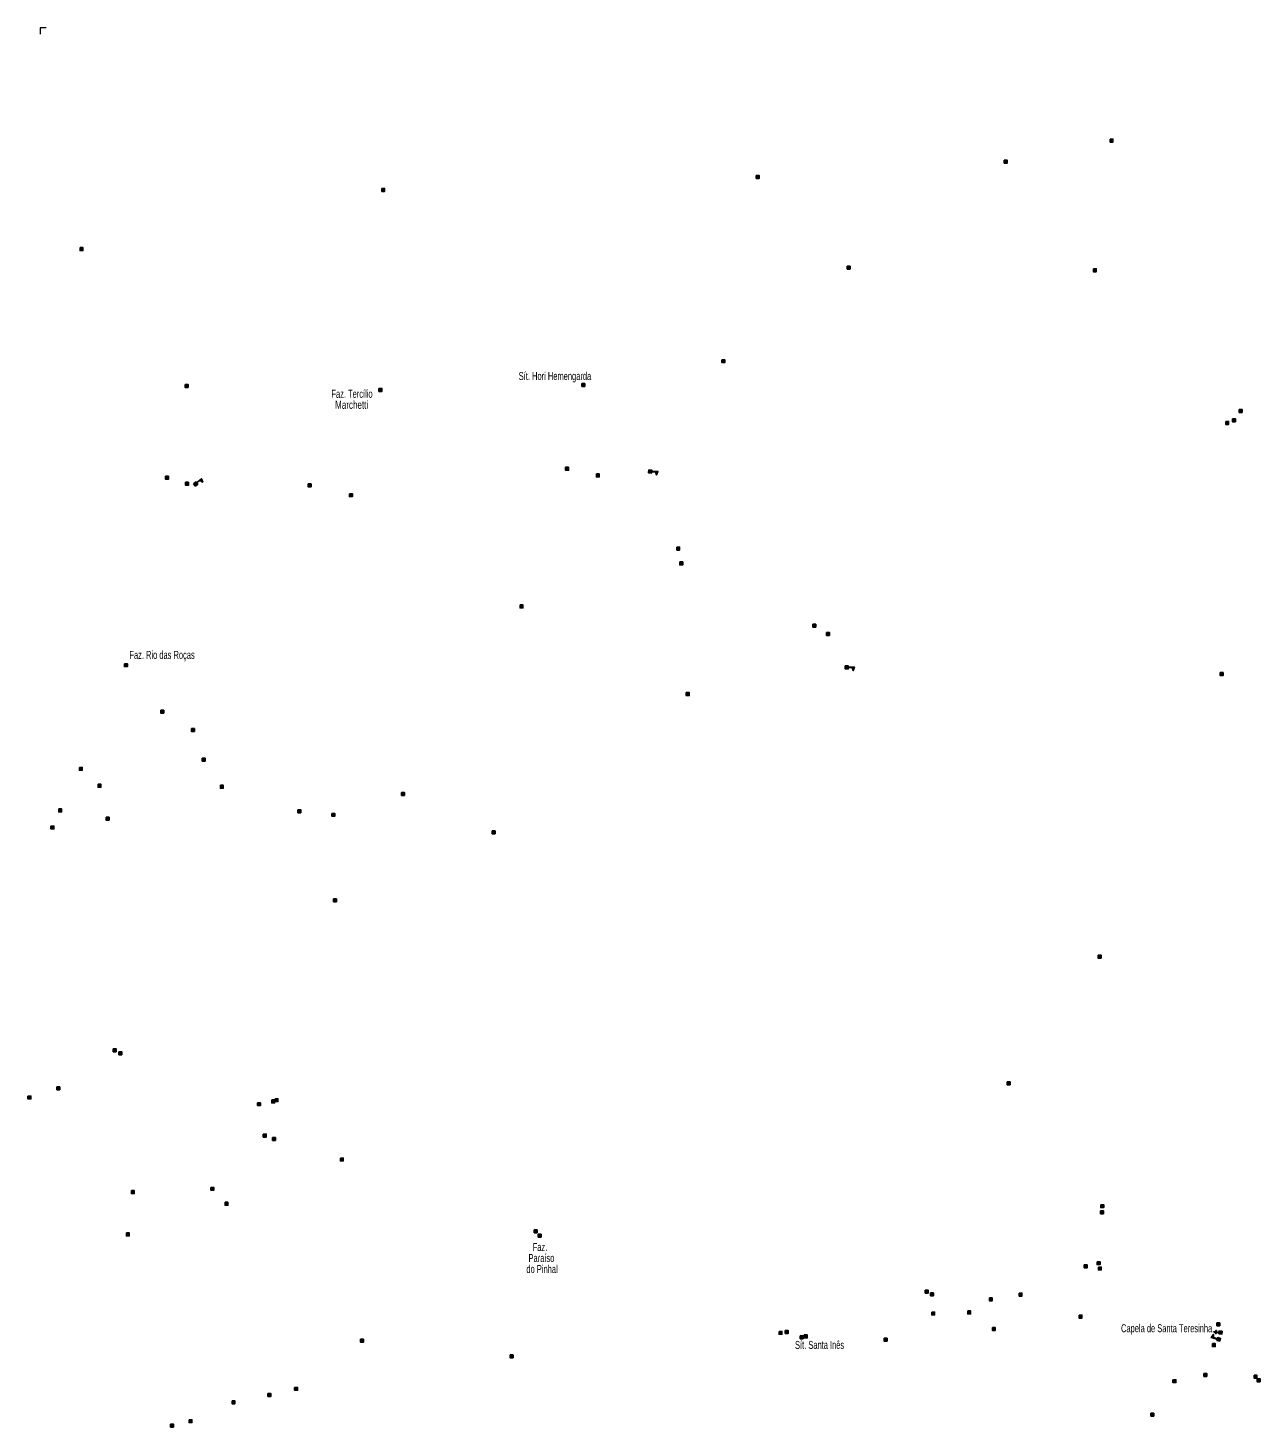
# Model space of a CAD drawing. Extents: x 649.2 to 674.4, y 7040 to 7068.1.
# Drawn here: x 649.37 to 661.68, y 7054.07 to 7068.06 of the extents above; entities that cross this region are included whole.
import ezdxf
from ezdxf.enums import TextEntityAlignment as Align

# ---------------------------------------------------------------- set-up
doc = ezdxf.new("R2010")
doc.units = 0
doc.header["$LTSCALE"] = 0.032
for name, color, linetype, lineweight in [('2', 7, 'Continuous', 25), ('4', 7, 'Continuous', 25), ('6', 7, 'Continuous', 25), ('63', 7, 'Continuous', 13)]:
    doc.layers.add(name, color=color, linetype=linetype, lineweight=lineweight)
doc.layers.add('61', color=7, linetype='Continuous')

msp = doc.modelspace()

# ---------------------------------------------------------------- hatches: boundary and pattern name
at = {"layer": '2'}
for points in [[(660.1834, 7066.9508), (660.2124, 7066.9508), (660.2124, 7066.9218), (660.1834, 7066.9218)], [(659.1263, 7066.7397), (659.1553, 7066.7397), (659.1553, 7066.7107), (659.1263, 7066.7107)], [(656.6475, 7066.5866), (656.6765, 7066.5866), (656.6765, 7066.5576), (656.6475, 7066.5576)], [(652.9028, 7066.4573), (652.9318, 7066.4573), (652.9318, 7066.4283), (652.9028, 7066.4283)], [(649.8868, 7065.866), (649.9158, 7065.866), (649.9158, 7065.837), (649.8868, 7065.837)], [(657.5563, 7065.6798), (657.5853, 7065.6798), (657.5853, 7065.6508), (657.5563, 7065.6508)], [(660.017, 7065.6539), (660.046, 7065.6539), (660.046, 7065.6249), (660.017, 7065.6249)], [(656.3032, 7064.7455), (656.3322, 7064.7455), (656.3322, 7064.7165), (656.3032, 7064.7165)], [(650.9374, 7064.498), (650.9664, 7064.498), (650.9664, 7064.469), (650.9374, 7064.469)], [(652.8752, 7064.4576), (652.9042, 7064.4576), (652.9042, 7064.4286), (652.8752, 7064.4286)], [(654.9037, 7064.5068), (654.9327, 7064.5068), (654.9327, 7064.4778), (654.9037, 7064.4778)], [(661.34, 7064.1278), (661.369, 7064.1278), (661.369, 7064.0988), (661.34, 7064.0988)], [(661.4079, 7064.1548), (661.4369, 7064.1548), (661.4369, 7064.1258), (661.4079, 7064.1258)], [(661.474, 7064.2479), (661.503, 7064.2479), (661.503, 7064.2189), (661.474, 7064.2189)], [(650.7419, 7063.5796), (650.7709, 7063.5796), (650.7709, 7063.5506), (650.7419, 7063.5506)], [(654.7412, 7063.6694), (654.7702, 7063.6694), (654.7702, 7063.6404), (654.7412, 7063.6404)], [(655.0488, 7063.6027), (655.0778, 7063.6027), (655.0778, 7063.5737), (655.0488, 7063.5737)], [(650.9419, 7063.5198), (650.9709, 7063.5198), (650.9709, 7063.4908), (650.9419, 7063.4908)], [(652.1674, 7063.5035), (652.1964, 7063.5035), (652.1964, 7063.4745), (652.1674, 7063.4745)], [(652.5802, 7063.406), (652.6092, 7063.406), (652.6092, 7063.377), (652.5802, 7063.377)], [(655.8518, 7062.8716), (655.8808, 7062.8716), (655.8808, 7062.8426), (655.8518, 7062.8426)], [(655.8824, 7062.7231), (655.9114, 7062.7231), (655.9114, 7062.6941), (655.8824, 7062.6941)], [(654.2856, 7062.2937), (654.3146, 7062.2937), (654.3146, 7062.2647), (654.2856, 7062.2647)], [(657.2126, 7062.1007), (657.2416, 7062.1007), (657.2416, 7062.0717), (657.2126, 7062.0717)], [(657.3488, 7062.0185), (657.3778, 7062.0185), (657.3778, 7061.9895), (657.3488, 7061.9895)], [(650.3309, 7061.7062), (650.3599, 7061.7062), (650.3599, 7061.6772), (650.3309, 7061.6772)], [(661.2847, 7061.6171), (661.3137, 7061.6171), (661.3137, 7061.5881), (661.2847, 7061.5881)], [(655.9473, 7061.4167), (655.9763, 7061.4167), (655.9763, 7061.3877), (655.9473, 7061.3877)], [(650.6944, 7061.2416), (650.7234, 7061.2416), (650.7234, 7061.2126), (650.6944, 7061.2126)], [(651.001, 7061.058), (651.03, 7061.058), (651.03, 7061.029), (651.001, 7061.029)], [(649.8801, 7060.6699), (649.9091, 7060.6699), (649.9091, 7060.6409), (649.8801, 7060.6409)], [(651.1092, 7060.7612), (651.1382, 7060.7612), (651.1382, 7060.7322), (651.1092, 7060.7322)], [(650.0672, 7060.5006), (650.0962, 7060.5006), (650.0962, 7060.4716), (650.0672, 7060.4716)], [(651.2895, 7060.4907), (651.3185, 7060.4907), (651.3185, 7060.4617), (651.2895, 7060.4617)], [(653.1014, 7060.4191), (653.1304, 7060.4191), (653.1304, 7060.3901), (653.1014, 7060.3901)], [(649.6739, 7060.2536), (649.7029, 7060.2536), (649.7029, 7060.2246), (649.6739, 7060.2246)], [(652.0647, 7060.2458), (652.0937, 7060.2458), (652.0937, 7060.2168), (652.0647, 7060.2168)], [(652.4044, 7060.2102), (652.4334, 7060.2102), (652.4334, 7060.1812), (652.4044, 7060.1812)], [(649.5962, 7060.083), (649.6252, 7060.083), (649.6252, 7060.054), (649.5962, 7060.054)], [(650.1487, 7060.1709), (650.1777, 7060.1709), (650.1777, 7060.1419), (650.1487, 7060.1419)], [(654.0066, 7060.0351), (654.0356, 7060.0351), (654.0356, 7060.0061), (654.0066, 7060.0061)], [(652.4213, 7059.3547), (652.4503, 7059.3547), (652.4503, 7059.3257), (652.4213, 7059.3257)], [(660.0644, 7058.7923), (660.0934, 7058.7923), (660.0934, 7058.7633), (660.0644, 7058.7633)], [(650.2189, 7057.8561), (650.2479, 7057.8561), (650.2479, 7057.8271), (650.2189, 7057.8271)], [(650.2753, 7057.8259), (650.3043, 7057.8259), (650.3043, 7057.7969), (650.2753, 7057.7969)], [(649.6558, 7057.4756), (649.6848, 7057.4756), (649.6848, 7057.4466), (649.6558, 7057.4466)], [(659.155, 7057.5266), (659.184, 7057.5266), (659.184, 7057.4976), (659.155, 7057.4976)], [(649.3665, 7057.384), (649.3955, 7057.384), (649.3955, 7057.355), (649.3665, 7057.355)], [(651.6616, 7057.317), (651.6906, 7057.317), (651.6906, 7057.288), (651.6616, 7057.288)], [(651.8034, 7057.3449), (651.8324, 7057.3449), (651.8324, 7057.3159), (651.8034, 7057.3159)], [(651.8365, 7057.3568), (651.8655, 7057.3568), (651.8655, 7057.3278), (651.8365, 7057.3278)], [(651.7186, 7057.0029), (651.7476, 7057.0029), (651.7476, 7056.9739), (651.7186, 7056.9739)], [(651.8114, 7056.9698), (651.8404, 7056.9698), (651.8404, 7056.9408), (651.8114, 7056.9408)], [(652.4896, 7056.7639), (652.5186, 7056.7639), (652.5186, 7056.7349), (652.4896, 7056.7349)], [(650.4005, 7056.4384), (650.4295, 7056.4384), (650.4295, 7056.4094), (650.4005, 7056.4094)], [(651.195, 7056.4706), (651.224, 7056.4706), (651.224, 7056.4416), (651.195, 7056.4416)], [(651.3364, 7056.3216), (651.3654, 7056.3216), (651.3654, 7056.2926), (651.3364, 7056.2926)], [(660.0915, 7056.2973), (660.1205, 7056.2973), (660.1205, 7056.2683), (660.0915, 7056.2683)], [(660.0884, 7056.2363), (660.1174, 7056.2363), (660.1174, 7056.2073), (660.0884, 7056.2073)], [(650.35, 7056.0147), (650.379, 7056.0147), (650.379, 7055.9857), (650.35, 7055.9857)], [(654.4274, 7056.0462), (654.4564, 7056.0462), (654.4564, 7056.0172), (654.4274, 7056.0172)], [(654.4677, 7056.0023), (654.4967, 7056.0023), (654.4967, 7055.9733), (654.4677, 7055.9733)], [(659.9262, 7055.6959), (659.9552, 7055.6959), (659.9552, 7055.6669), (659.9262, 7055.6669)], [(660.0549, 7055.7271), (660.0839, 7055.7271), (660.0839, 7055.6981), (660.0549, 7055.6981)], [(660.0667, 7055.674), (660.0957, 7055.674), (660.0957, 7055.645), (660.0667, 7055.645)], [(658.3357, 7055.4436), (658.3647, 7055.4436), (658.3647, 7055.4146), (658.3357, 7055.4146)], [(658.389, 7055.4164), (658.418, 7055.4164), (658.418, 7055.3874), (658.389, 7055.3874)], [(658.9776, 7055.3656), (659.0066, 7055.3656), (659.0066, 7055.3366), (658.9776, 7055.3366)], [(659.2736, 7055.4138), (659.3026, 7055.4138), (659.3026, 7055.3848), (659.2736, 7055.3848)], [(658.4009, 7055.2248), (658.4299, 7055.2248), (658.4299, 7055.1958), (658.4009, 7055.1958)], [(658.7611, 7055.2351), (658.7901, 7055.2351), (658.7901, 7055.2061), (658.7611, 7055.2061)], [(659.8735, 7055.1934), (659.9025, 7055.1934), (659.9025, 7055.1644), (659.8735, 7055.1644)], [(656.9372, 7055.0396), (656.9662, 7055.0396), (656.9662, 7055.0106), (656.9372, 7055.0106)], [(659.0076, 7055.0695), (659.0366, 7055.0695), (659.0366, 7055.0405), (659.0076, 7055.0405)], [(661.2519, 7055.1157), (661.2809, 7055.1157), (661.2809, 7055.0867), (661.2519, 7055.0867)], [(652.6913, 7054.9523), (652.7203, 7054.9523), (652.7203, 7054.9233), (652.6913, 7054.9233)], [(656.8746, 7055.0309), (656.9036, 7055.0309), (656.9036, 7055.0019), (656.8746, 7055.0019)], [(657.0866, 7054.9858), (657.1156, 7054.9858), (657.1156, 7054.9568), (657.0866, 7054.9568)], [(657.127, 7054.9952), (657.156, 7054.9952), (657.156, 7054.9662), (657.127, 7054.9662)], [(657.925, 7054.9623), (657.954, 7054.9623), (657.954, 7054.9333), (657.925, 7054.9333)], [(661.2066, 7054.9085), (661.2356, 7054.9085), (661.2356, 7054.8795), (661.2066, 7054.8795)], [(654.1863, 7054.7962), (654.2153, 7054.7962), (654.2153, 7054.7672), (654.1863, 7054.7672)], [(660.8128, 7054.5476), (660.8418, 7054.5476), (660.8418, 7054.5186), (660.8128, 7054.5186)], [(661.1216, 7054.6107), (661.1506, 7054.6107), (661.1506, 7054.5817), (661.1216, 7054.5817)], [(661.6238, 7054.5929), (661.6528, 7054.5929), (661.6528, 7054.5639), (661.6238, 7054.5639)], [(661.654, 7054.5572), (661.683, 7054.5572), (661.683, 7054.5282), (661.654, 7054.5282)], [(651.4061, 7054.3365), (651.4351, 7054.3365), (651.4351, 7054.3075), (651.4061, 7054.3075)], [(651.7656, 7054.4096), (651.7946, 7054.4096), (651.7946, 7054.3806), (651.7656, 7054.3806)], [(652.032, 7054.471), (652.061, 7054.471), (652.061, 7054.442), (652.032, 7054.442)], [(660.592, 7054.2125), (660.621, 7054.2125), (660.621, 7054.1835), (660.592, 7054.1835)], [(650.792, 7054.104), (650.821, 7054.104), (650.821, 7054.075), (650.792, 7054.075)], [(650.9767, 7054.1476), (651.0057, 7054.1476), (651.0057, 7054.1186), (650.9767, 7054.1186)]]:
    msp.add_hatch(color=256, dxfattribs=at).paths.add_polyline_path(points)
at = {"layer": '4'}
for points in [[(655.5717, 7063.6429), (655.6017, 7063.6422), (655.601, 7063.6122), (655.571, 7063.6129)], [(651.0219, 7063.5044), (651.0445, 7063.5241), (651.0643, 7063.5015), (651.0417, 7063.4818)], [(657.5364, 7061.6845), (657.5664, 7061.6847), (657.5666, 7061.6547), (657.5366, 7061.6545)], [(661.2804, 7054.9321), (661.2516, 7054.9405), (661.26, 7054.9693), (661.2888, 7054.9609)]]:
    msp.add_hatch(color=256, dxfattribs=at).paths.add_polyline_path(points)
at = {"layer": '6'}
for points in [[(661.273, 7055.0236), (661.2726, 7055.0186), (661.2452, 7055.0214), (661.2439, 7055.0089), (661.2389, 7055.0095), (661.2402, 7055.0218), (661.2228, 7055.0237), (661.2233, 7055.0286), (661.2407, 7055.0268), (661.242, 7055.0393), (661.2469, 7055.0388), (661.2457, 7055.0264)], [(661.2713, 7055.0062), (661.3012, 7055.0031), (661.3042, 7055.033), (661.2743, 7055.036)]]:
    msp.add_hatch(color=256, dxfattribs=at).paths.add_polyline_path(points)

# ---------------------------------------------------------------- linework, layer by layer
at = {"layer": '2'}
for points in [[(660.1834, 7066.9508), (660.2124, 7066.9508), (660.2124, 7066.9218), (660.1834, 7066.9218)], [(659.1263, 7066.7397), (659.1553, 7066.7397), (659.1553, 7066.7107), (659.1263, 7066.7107)], [(656.6475, 7066.5866), (656.6765, 7066.5866), (656.6765, 7066.5576), (656.6475, 7066.5576)], [(652.9028, 7066.4573), (652.9318, 7066.4573), (652.9318, 7066.4283), (652.9028, 7066.4283)], [(649.8868, 7065.866), (649.9158, 7065.866), (649.9158, 7065.837), (649.8868, 7065.837)], [(657.5563, 7065.6798), (657.5853, 7065.6798), (657.5853, 7065.6508), (657.5563, 7065.6508)], [(660.017, 7065.6539), (660.046, 7065.6539), (660.046, 7065.6249), (660.017, 7065.6249)], [(656.3032, 7064.7455), (656.3322, 7064.7455), (656.3322, 7064.7165), (656.3032, 7064.7165)], [(650.9374, 7064.498), (650.9664, 7064.498), (650.9664, 7064.469), (650.9374, 7064.469)], [(652.8752, 7064.4576), (652.9042, 7064.4576), (652.9042, 7064.4286), (652.8752, 7064.4286)], [(654.9037, 7064.5068), (654.9327, 7064.5068), (654.9327, 7064.4778), (654.9037, 7064.4778)], [(661.34, 7064.1278), (661.369, 7064.1278), (661.369, 7064.0988), (661.34, 7064.0988)], [(661.4079, 7064.1548), (661.4369, 7064.1548), (661.4369, 7064.1258), (661.4079, 7064.1258)], [(661.474, 7064.2479), (661.503, 7064.2479), (661.503, 7064.2189), (661.474, 7064.2189)], [(650.7419, 7063.5796), (650.7709, 7063.5796), (650.7709, 7063.5506), (650.7419, 7063.5506)], [(654.7412, 7063.6694), (654.7702, 7063.6694), (654.7702, 7063.6404), (654.7412, 7063.6404)], [(655.0488, 7063.6027), (655.0778, 7063.6027), (655.0778, 7063.5737), (655.0488, 7063.5737)], [(650.9419, 7063.5198), (650.9709, 7063.5198), (650.9709, 7063.4908), (650.9419, 7063.4908)], [(652.1674, 7063.5035), (652.1964, 7063.5035), (652.1964, 7063.4745), (652.1674, 7063.4745)], [(652.5802, 7063.406), (652.6092, 7063.406), (652.6092, 7063.377), (652.5802, 7063.377)], [(655.8518, 7062.8716), (655.8808, 7062.8716), (655.8808, 7062.8426), (655.8518, 7062.8426)], [(655.8824, 7062.7231), (655.9114, 7062.7231), (655.9114, 7062.6941), (655.8824, 7062.6941)], [(654.2856, 7062.2937), (654.3146, 7062.2937), (654.3146, 7062.2647), (654.2856, 7062.2647)], [(657.2126, 7062.1007), (657.2416, 7062.1007), (657.2416, 7062.0717), (657.2126, 7062.0717)], [(657.3488, 7062.0185), (657.3778, 7062.0185), (657.3778, 7061.9895), (657.3488, 7061.9895)], [(650.3309, 7061.7062), (650.3599, 7061.7062), (650.3599, 7061.6772), (650.3309, 7061.6772)], [(661.2847, 7061.6171), (661.3137, 7061.6171), (661.3137, 7061.5881), (661.2847, 7061.5881)], [(655.9473, 7061.4167), (655.9763, 7061.4167), (655.9763, 7061.3877), (655.9473, 7061.3877)], [(650.6944, 7061.2416), (650.7234, 7061.2416), (650.7234, 7061.2126), (650.6944, 7061.2126)], [(651.001, 7061.058), (651.03, 7061.058), (651.03, 7061.029), (651.001, 7061.029)], [(649.8801, 7060.6699), (649.9091, 7060.6699), (649.9091, 7060.6409), (649.8801, 7060.6409)], [(651.1092, 7060.7612), (651.1382, 7060.7612), (651.1382, 7060.7322), (651.1092, 7060.7322)], [(650.0672, 7060.5006), (650.0962, 7060.5006), (650.0962, 7060.4716), (650.0672, 7060.4716)], [(651.2895, 7060.4907), (651.3185, 7060.4907), (651.3185, 7060.4617), (651.2895, 7060.4617)], [(653.1014, 7060.4191), (653.1304, 7060.4191), (653.1304, 7060.3901), (653.1014, 7060.3901)], [(649.6739, 7060.2536), (649.7029, 7060.2536), (649.7029, 7060.2246), (649.6739, 7060.2246)], [(652.0647, 7060.2458), (652.0937, 7060.2458), (652.0937, 7060.2168), (652.0647, 7060.2168)], [(652.4044, 7060.2102), (652.4334, 7060.2102), (652.4334, 7060.1812), (652.4044, 7060.1812)], [(649.5962, 7060.083), (649.6252, 7060.083), (649.6252, 7060.054), (649.5962, 7060.054)], [(650.1487, 7060.1709), (650.1777, 7060.1709), (650.1777, 7060.1419), (650.1487, 7060.1419)], [(654.0066, 7060.0351), (654.0356, 7060.0351), (654.0356, 7060.0061), (654.0066, 7060.0061)], [(652.4213, 7059.3547), (652.4503, 7059.3547), (652.4503, 7059.3257), (652.4213, 7059.3257)], [(660.0644, 7058.7923), (660.0934, 7058.7923), (660.0934, 7058.7633), (660.0644, 7058.7633)], [(650.2189, 7057.8561), (650.2479, 7057.8561), (650.2479, 7057.8271), (650.2189, 7057.8271)], [(650.2753, 7057.8259), (650.3043, 7057.8259), (650.3043, 7057.7969), (650.2753, 7057.7969)], [(649.6558, 7057.4756), (649.6848, 7057.4756), (649.6848, 7057.4466), (649.6558, 7057.4466)], [(659.155, 7057.5266), (659.184, 7057.5266), (659.184, 7057.4976), (659.155, 7057.4976)], [(649.3665, 7057.384), (649.3955, 7057.384), (649.3955, 7057.355), (649.3665, 7057.355)], [(651.6616, 7057.317), (651.6906, 7057.317), (651.6906, 7057.288), (651.6616, 7057.288)], [(651.8034, 7057.3449), (651.8324, 7057.3449), (651.8324, 7057.3159), (651.8034, 7057.3159)], [(651.8365, 7057.3568), (651.8655, 7057.3568), (651.8655, 7057.3278), (651.8365, 7057.3278)], [(651.7186, 7057.0029), (651.7476, 7057.0029), (651.7476, 7056.9739), (651.7186, 7056.9739)], [(651.8114, 7056.9698), (651.8404, 7056.9698), (651.8404, 7056.9408), (651.8114, 7056.9408)], [(652.4896, 7056.7639), (652.5186, 7056.7639), (652.5186, 7056.7349), (652.4896, 7056.7349)], [(650.4005, 7056.4384), (650.4295, 7056.4384), (650.4295, 7056.4094), (650.4005, 7056.4094)], [(651.195, 7056.4706), (651.224, 7056.4706), (651.224, 7056.4416), (651.195, 7056.4416)], [(651.3364, 7056.3216), (651.3654, 7056.3216), (651.3654, 7056.2926), (651.3364, 7056.2926)], [(660.0915, 7056.2973), (660.1205, 7056.2973), (660.1205, 7056.2683), (660.0915, 7056.2683)], [(660.0884, 7056.2363), (660.1174, 7056.2363), (660.1174, 7056.2073), (660.0884, 7056.2073)], [(650.35, 7056.0147), (650.379, 7056.0147), (650.379, 7055.9857), (650.35, 7055.9857)], [(654.4274, 7056.0462), (654.4564, 7056.0462), (654.4564, 7056.0172), (654.4274, 7056.0172)], [(654.4677, 7056.0023), (654.4967, 7056.0023), (654.4967, 7055.9733), (654.4677, 7055.9733)], [(659.9262, 7055.6959), (659.9552, 7055.6959), (659.9552, 7055.6669), (659.9262, 7055.6669)], [(660.0549, 7055.7271), (660.0839, 7055.7271), (660.0839, 7055.6981), (660.0549, 7055.6981)], [(660.0667, 7055.674), (660.0957, 7055.674), (660.0957, 7055.645), (660.0667, 7055.645)], [(658.3357, 7055.4436), (658.3647, 7055.4436), (658.3647, 7055.4146), (658.3357, 7055.4146)], [(658.389, 7055.4164), (658.418, 7055.4164), (658.418, 7055.3874), (658.389, 7055.3874)], [(658.9776, 7055.3656), (659.0066, 7055.3656), (659.0066, 7055.3366), (658.9776, 7055.3366)], [(659.2736, 7055.4138), (659.3026, 7055.4138), (659.3026, 7055.3848), (659.2736, 7055.3848)], [(658.4009, 7055.2248), (658.4299, 7055.2248), (658.4299, 7055.1958), (658.4009, 7055.1958)], [(658.7611, 7055.2351), (658.7901, 7055.2351), (658.7901, 7055.2061), (658.7611, 7055.2061)], [(659.8735, 7055.1934), (659.9025, 7055.1934), (659.9025, 7055.1644), (659.8735, 7055.1644)], [(656.9372, 7055.0396), (656.9662, 7055.0396), (656.9662, 7055.0106), (656.9372, 7055.0106)], [(659.0076, 7055.0695), (659.0366, 7055.0695), (659.0366, 7055.0405), (659.0076, 7055.0405)], [(661.2519, 7055.1157), (661.2809, 7055.1157), (661.2809, 7055.0867), (661.2519, 7055.0867)], [(652.6913, 7054.9523), (652.7203, 7054.9523), (652.7203, 7054.9233), (652.6913, 7054.9233)], [(656.8746, 7055.0309), (656.9036, 7055.0309), (656.9036, 7055.0019), (656.8746, 7055.0019)], [(657.0866, 7054.9858), (657.1156, 7054.9858), (657.1156, 7054.9568), (657.0866, 7054.9568)], [(657.127, 7054.9952), (657.156, 7054.9952), (657.156, 7054.9662), (657.127, 7054.9662)], [(657.925, 7054.9623), (657.954, 7054.9623), (657.954, 7054.9333), (657.925, 7054.9333)], [(661.2066, 7054.9085), (661.2356, 7054.9085), (661.2356, 7054.8795), (661.2066, 7054.8795)], [(654.1863, 7054.7962), (654.2153, 7054.7962), (654.2153, 7054.7672), (654.1863, 7054.7672)], [(660.8128, 7054.5476), (660.8418, 7054.5476), (660.8418, 7054.5186), (660.8128, 7054.5186)], [(661.1216, 7054.6107), (661.1506, 7054.6107), (661.1506, 7054.5817), (661.1216, 7054.5817)], [(661.6238, 7054.5929), (661.6528, 7054.5929), (661.6528, 7054.5639), (661.6238, 7054.5639)], [(661.654, 7054.5572), (661.683, 7054.5572), (661.683, 7054.5282), (661.654, 7054.5282)], [(651.4061, 7054.3365), (651.4351, 7054.3365), (651.4351, 7054.3075), (651.4061, 7054.3075)], [(651.7656, 7054.4096), (651.7946, 7054.4096), (651.7946, 7054.3806), (651.7656, 7054.3806)], [(652.032, 7054.471), (652.061, 7054.471), (652.061, 7054.442), (652.032, 7054.442)], [(660.592, 7054.2125), (660.621, 7054.2125), (660.621, 7054.1835), (660.592, 7054.1835)], [(650.792, 7054.104), (650.821, 7054.104), (650.821, 7054.075), (650.792, 7054.075)], [(650.9767, 7054.1476), (651.0057, 7054.1476), (651.0057, 7054.1186), (650.9767, 7054.1186)]]:
    msp.add_lwpolyline(points, close=True, dxfattribs=at)
at = {"layer": '4'}
for p, q in [((655.6014, 7063.6297), (655.6013, 7063.6247)), ((651.0527, 7063.5147), (651.056, 7063.511)), ((657.5665, 7061.6722), (657.5665, 7061.6672)), ((661.2551, 7054.9525), (661.2565, 7054.9573))]:
    msp.add_line(p, q, dxfattribs=at)
for points in [[(655.5717, 7063.6429), (655.6017, 7063.6422), (655.601, 7063.6122), (655.571, 7063.6129)], [(655.6014, 7063.6297), (655.6639, 7063.6283), (655.6506, 7063.5936), (655.6408, 7063.6238), (655.6013, 7063.6247)], [(651.0219, 7063.5044), (651.0445, 7063.5241), (651.0643, 7063.5015), (651.0417, 7063.4818)], [(651.0527, 7063.5147), (651.0998, 7063.5559), (651.1134, 7063.5213), (651.0858, 7063.537), (651.056, 7063.511)], [(657.5364, 7061.6845), (657.5664, 7061.6847), (657.5666, 7061.6547), (657.5366, 7061.6545)], [(657.5665, 7061.6722), (657.629, 7061.6727), (657.6167, 7061.6376), (657.606, 7061.6675), (657.5665, 7061.6672)], [(661.2551, 7054.9525), (661.1951, 7054.9699), (661.2169, 7055.0001), (661.2186, 7054.9683), (661.2565, 7054.9573)], [(661.2804, 7054.9321), (661.2516, 7054.9405), (661.26, 7054.9693), (661.2888, 7054.9609)]]:
    msp.add_lwpolyline(points, close=True, dxfattribs=at)
at = {"layer": '6'}
for points in [[(661.273, 7055.0236), (661.2726, 7055.0186), (661.2452, 7055.0214), (661.2439, 7055.0089), (661.2389, 7055.0095), (661.2402, 7055.0218), (661.2228, 7055.0237), (661.2233, 7055.0286), (661.2407, 7055.0268), (661.242, 7055.0393), (661.2469, 7055.0388), (661.2457, 7055.0264)], [(661.2713, 7055.0062), (661.3012, 7055.0031), (661.3042, 7055.033), (661.2743, 7055.036)]]:
    msp.add_lwpolyline(points, close=True, dxfattribs=at)
at = {"layer": '63'}
msp.add_lwpolyline([(649.5487, 7068.0617), (649.4871, 7068.0617), (649.4871, 7068.001)], dxfattribs=at)

# ---------------------------------------------------------------- texts
at = {"layer": '61'}
for s, width, p in [('Sít. Hori Hemengarda', 0.7, (654.9967, 7064.5422)), ('Faz. Tercílio', 0.7, (652.8116, 7064.3644)), ('Marchetti  ', 0.75, (652.8116, 7064.2544)), ('Capela de Santa Teresinha', 0.7, (661.2053, 7055.0226))]:
    msp.add_text(s, height=0.08, dxfattribs=dict(at, width=width)).set_placement(p, align=Align.RIGHT)
at = {"layer": '61', "width": 0.7}
for s, p in [('Faz. Rio das Roças', (650.3801, 7061.7542)), ('     Faz.', (654.3079, 7055.8347)), ('   Paraíso', (654.3079, 7055.7247)), ('  do Pinhal  ', (654.3079, 7055.6147)), ('Sít. Santa Inês', (657.0345, 7054.8557))]:
    msp.add_text(s, height=0.08, dxfattribs=at).set_placement(p)

doc.saveas('drawing.dxf')
